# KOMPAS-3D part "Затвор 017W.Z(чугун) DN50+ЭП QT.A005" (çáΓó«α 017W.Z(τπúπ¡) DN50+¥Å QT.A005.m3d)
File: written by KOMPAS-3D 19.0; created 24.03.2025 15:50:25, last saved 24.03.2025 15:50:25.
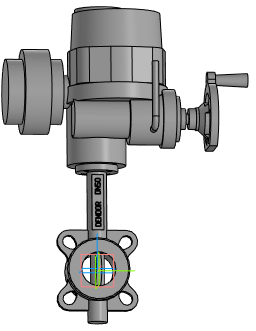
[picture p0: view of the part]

Document properties: Полное имя файла: Затвор 017W.Z(чугун) DN50+ЭП QT.A005.a3d

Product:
- Part/product: Затвор 017W.Z(чугун) DN50+ЭП QT.A005
    Масса: 39.0295

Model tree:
1. Операция без истории:1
